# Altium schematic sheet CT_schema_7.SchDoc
size 308 x 210 mm
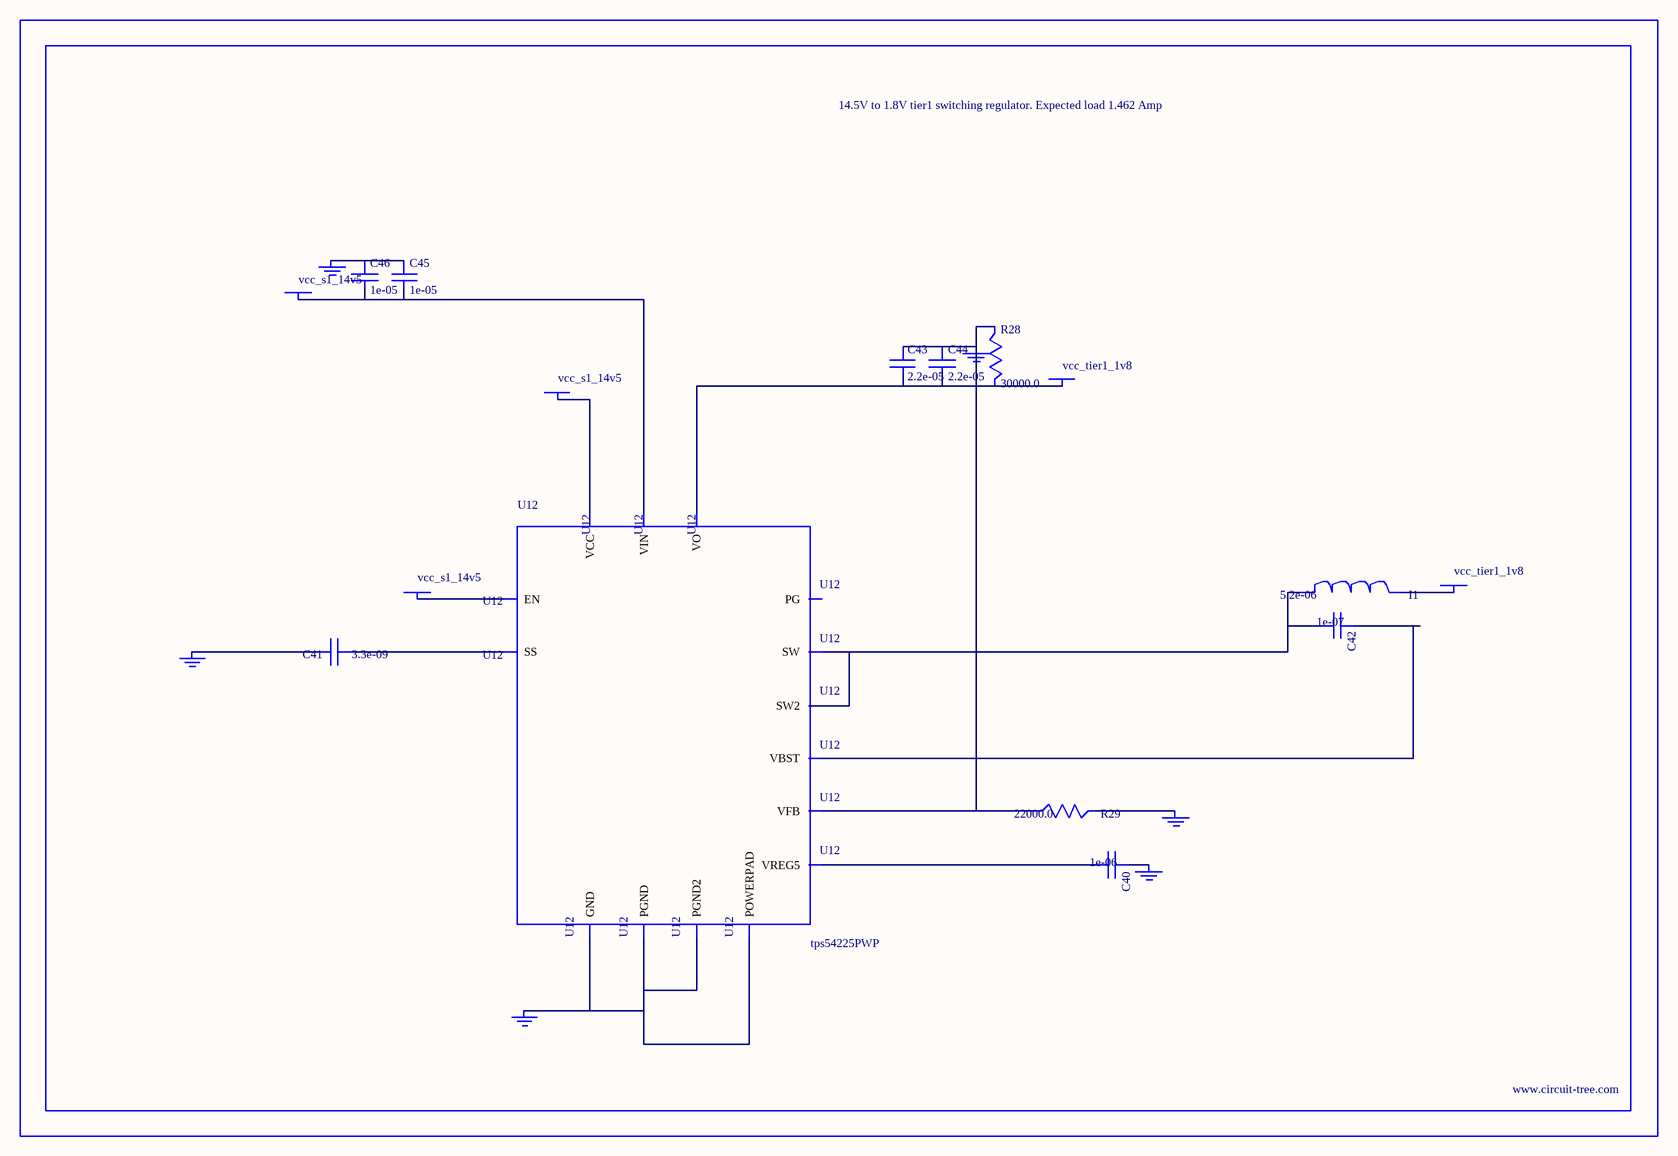
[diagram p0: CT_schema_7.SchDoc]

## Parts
BORDER6  (no value)
C40  1e-06  [C0603]
C41  3.3e-09  [C0402]
C42  1e-07  [C0402]
C43  2.2e-05  [C1210]
C44  2.2e-05  [C1210]
C45  1e-05  [C1206]
C46  1e-05  [C1206]
GND_INSTANCE_6_0  (no value)
GND_INSTANCE_6_1  (no value)
GND_INSTANCE_6_2  (no value)
GND_INSTANCE_6_3  (no value)
GND_INSTANCE_6_4  (no value)
GND_INSTANCE_6_5  (no value)
I1  5.2e-06  [DR1040]
POWER_INSTANCE_6_0  vcc_tier1_1v8
POWER_INSTANCE_6_1  vcc_s1_14v5
POWER_INSTANCE_6_2  vcc_tier1_1v8
POWER_INSTANCE_6_3  vcc_s1_14v5
POWER_INSTANCE_6_4  vcc_s1_14v5
R28  30000.0  [R0603]
R29  22000.0  [R0603]
U12  tps54225PWP  [HTSSOP14]

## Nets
NetC40_1: C40.1 GND_INSTANCE_6_2.0(GND)
NetC40_2: C40.2 U12.3(VREG5)
NetC41_1: C41.1 U12.4(SS)
NetC41_2: C41.2 GND_INSTANCE_6_3.0(GND)
NetC42_1: C42.1 U12.12(VBST)
NetC42_2: C42.2 I1.1 U12.10(SW) U12.11(SW2)
NetC43_1: C43.1 C44.1 GND_INSTANCE_6_0.0(GND) R28.1 R29.1 U12.2(VFB)
NetC43_2: C43.2 C44.2 POWER_INSTANCE_6_0.0(PWR) R28.2 U12.1(VO)
NetC45_1: C45.1 C46.1 GND_INSTANCE_6_5.0(GND)
NetC45_2: C45.2 C46.2 POWER_INSTANCE_6_3.0(PWR) U12.13(VIN)
NetGND_INSTANCE_6_1_0: GND_INSTANCE_6_1.0(GND) R29.2
NetGND_INSTANCE_6_4_0: GND_INSTANCE_6_4.0(GND) U12.5(GND) U12.8(PGND) U12.9(PGND2) U12.15(POWERPAD)
NetI1_2: I1.2 POWER_INSTANCE_6_2.0(PWR)
NetPOWER_INSTANCE_6_1_0: POWER_INSTANCE_6_1.0(PWR) U12.7(EN)
NetPOWER_INSTANCE_6_4_0: POWER_INSTANCE_6_4.0(PWR) U12.14(VCC)

Not connected (* = marked no-connect by the designer): U12 6(PG)

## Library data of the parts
BORDER6 = BORDER_PAGE6
C40 = C0603C105K3RACTU
C41 = C0402C332K3RAC
C42 = C0402C104K3RACTU
C43 C44 = GRM32ER61E226ME15L
C45 C46 = C1206C106K3RACTU
GND_INSTANCE_6_0-GND_INSTANCE_6_5 = GND
I1 = DR1040-5R2-R
POWER_INSTANCE_6_0-POWER_INSTANCE_6_4 = PWR
R28 = RC0603JR-0730KL
R29 = RC0603JR-0722KL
